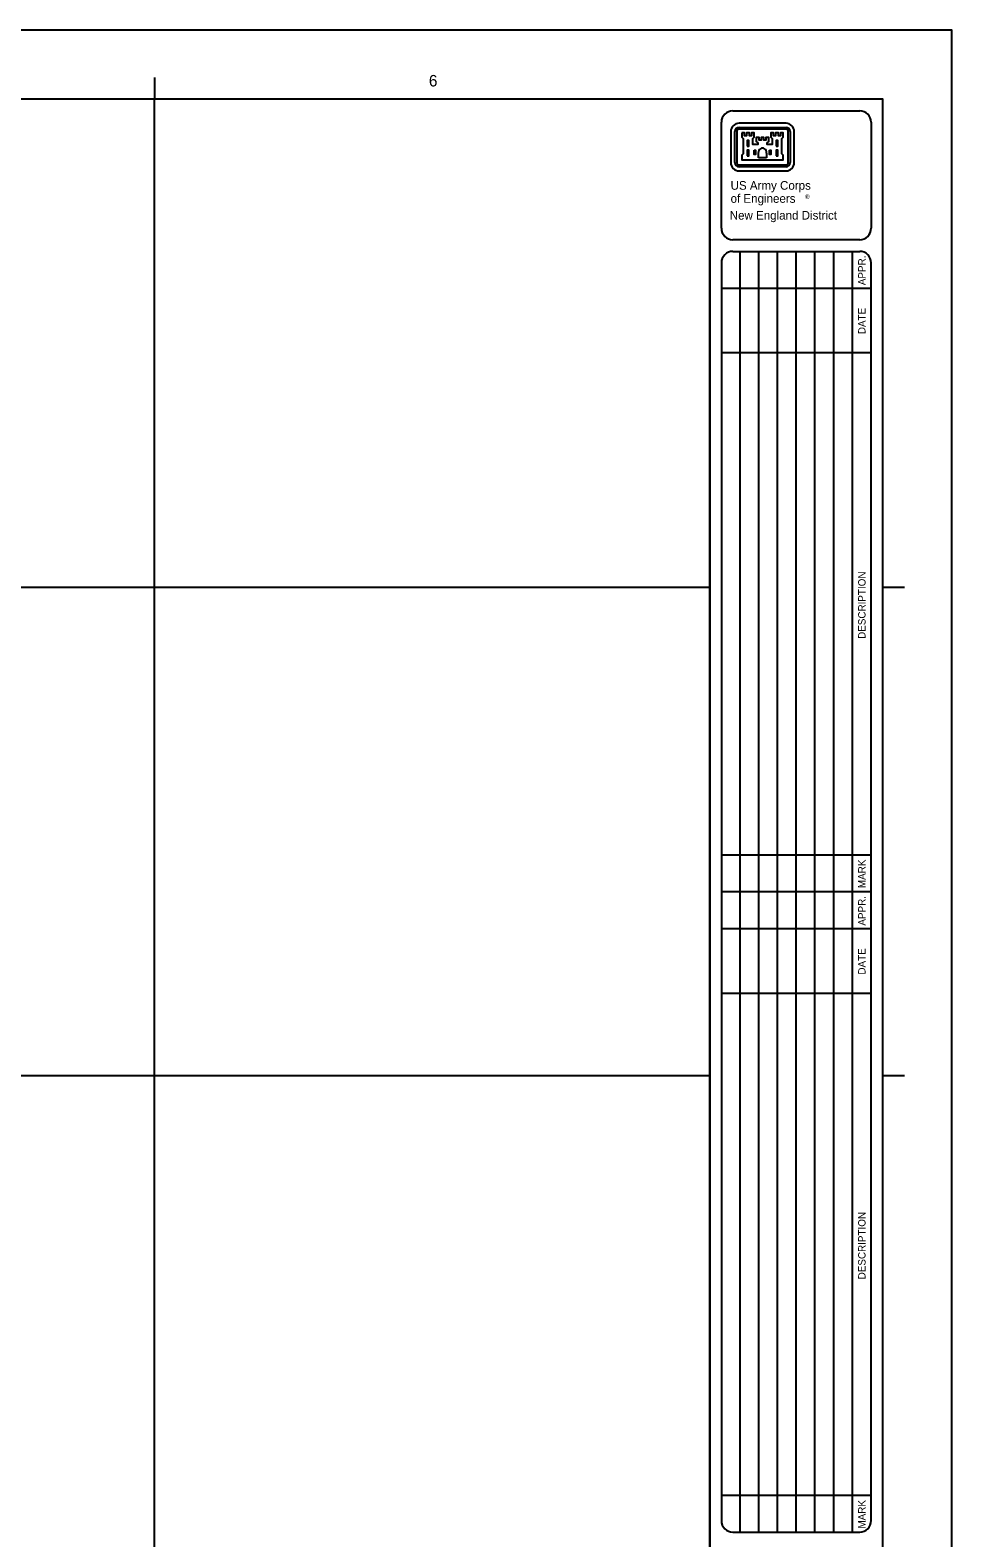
# Model space of a CAD drawing. Extents: x 0 to 3.33, y 0 to 2.33.
# Drawn here: x 2.5 to 3.333, y 0.97 to 2.333 of the extents above; entities that cross this region are included whole.
import ezdxf

# ---------------------------------------------------------------- set-up
doc = ezdxf.new("R2010")
doc.units = 0
for name, color, linetype in [('G-ANNO-NPLT', 7, 'Continuous'), ('G-ANNO-SYMB', 7, 'Continuous'), ('G-ANNO-TEXT', 7, 'Continuous'), ('G-ANNO-TTLB', 7, 'Continuous'), ('G-ANNO-TTLB-GRID', 7, 'Continuous')]:
    doc.layers.add(name, color=color, linetype=linetype)

msp = doc.modelspace()

# ---------------------------------------------------------------- linework, layer by layer
at = {"layer": 'G-ANNO-NPLT'}
msp.add_lwpolyline([(0, 0), (3.3333, 0), (3.3333, 2.3333), (0, 2.3333)], close=True, dxfattribs=at)
at = {"layer": 'G-ANNO-SYMB'}
for p, q in [((3.1334, 2.2416), (3.1334, 2.2135)), ((3.1372, 2.2135), (3.1372, 2.2416)), ((3.1372, 2.2416), (3.1372, 2.2416)), ((3.1388, 2.2416), (3.1388, 2.2135)), ((3.1834, 2.2491), (3.1409, 2.2491)), ((3.1409, 2.2491), (3.1409, 2.2491)), ((3.1409, 2.2454), (3.1834, 2.2454)), ((3.1834, 2.2437), (3.1409, 2.2437)), ((3.1834, 2.2437), (3.1834, 2.2437)), ((3.1855, 2.2135), (3.1855, 2.2416)), ((3.1871, 2.2416), (3.1871, 2.2135)), ((3.1908, 2.2135), (3.1908, 2.2416)), ((3.1409, 2.2114), (3.1834, 2.2114)), ((3.1834, 2.2098), (3.1409, 2.2098)), ((3.1584, 2.2179), (3.1584, 2.2221)), ((3.1659, 2.2179), (3.1584, 2.2179)), ((3.1659, 2.2221), (3.1659, 2.2179)), ((3.1409, 2.206), (3.1834, 2.206))]:
    msp.add_line(p, q, dxfattribs=at)
for points in [[(3.1434, 2.2404), (3.1434, 2.2366), (3.1447, 2.2354), (3.1447, 2.2216), (3.1434, 2.2204), (3.1434, 2.216), (3.1809, 2.216), (3.1809, 2.2204), (3.1796, 2.2216), (3.1796, 2.2354), (3.1809, 2.2366), (3.1809, 2.2404), (3.1784, 2.2404), (3.1784, 2.2379), (3.1765, 2.2379), (3.1765, 2.2404), (3.174, 2.2404), (3.174, 2.2379), (3.1721, 2.2379), (3.1721, 2.2404), (3.1696, 2.2404), (3.1696, 2.2366), (3.1709, 2.2354), (3.1709, 2.2298), (3.1665, 2.2298), (3.1665, 2.2313), (3.1678, 2.2326), (3.1678, 2.2363), (3.1653, 2.2363), (3.1653, 2.2338), (3.1634, 2.2338), (3.1634, 2.2363), (3.1609, 2.2363), (3.1609, 2.2338), (3.159, 2.2338), (3.159, 2.2363), (3.1565, 2.2363), (3.1565, 2.2326), (3.1578, 2.2313), (3.1578, 2.2298), (3.1534, 2.2298), (3.1534, 2.2354), (3.1546, 2.2366), (3.1546, 2.2404), (3.1522, 2.2404), (3.1522, 2.2379), (3.1503, 2.2379), (3.1503, 2.2404), (3.1478, 2.2404), (3.1478, 2.2379), (3.1459, 2.2379), (3.1459, 2.2404), (3.1434, 2.2404)], [(3.1484, 2.2285), (3.1497, 2.2285), (3.1497, 2.2335), (3.1484, 2.2335), (3.1484, 2.2285)], [(3.1484, 2.2198), (3.1497, 2.2198), (3.1497, 2.2248), (3.1484, 2.2248), (3.1484, 2.2198)], [(3.1546, 2.2248), (3.1559, 2.2248), (3.1559, 2.221), (3.1546, 2.221), (3.1546, 2.2248)], [(3.1684, 2.2248), (3.1696, 2.2248), (3.1696, 2.221), (3.1684, 2.221), (3.1684, 2.2248)], [(3.1746, 2.2335), (3.1747, 2.2335)], [(3.1746, 2.2285), (3.1759, 2.2285), (3.1759, 2.2335), (3.1746, 2.2335), (3.1746, 2.2285)], [(3.1746, 2.2198), (3.1759, 2.2198), (3.1759, 2.2248), (3.1746, 2.2248), (3.1746, 2.2198)], [(3.1758, 2.2285), (3.1759, 2.2286)]]:
    msp.add_lwpolyline(points, dxfattribs=at)
for centre, radius, start, end in [((3.1409, 2.2416), 0.00749, 90, 180), ((3.1409, 2.2416), 0.00375, 90, 180), ((3.1409, 2.2416), 0.0021, 90, 180), ((3.1834, 2.2416), 0.00749, 0, 90), ((3.1834, 2.2416), 0.00375, 0, 90), ((3.1834, 2.2416), 0.0021, 0, 90), ((3.1409, 2.2135), 0.00749, 180, 270), ((3.1409, 2.2135), 0.00375, 180, 270), ((3.1409, 2.2135), 0.0021, 180, 270), ((3.1834, 2.2135), 0.00749, 270, 360), ((3.1834, 2.2135), 0.00375, 270, 360), ((3.1834, 2.2135), 0.0021, 270, 360)]:
    msp.add_arc(centre, radius, start, end, dxfattribs=at)
msp.add_ellipse((3.1621, 2.2221), major_axis=(0, 0.00452), ratio=0.827815, start_param=4.712389, end_param=7.853982, dxfattribs=at)
at = {"layer": 'G-ANNO-TTLB'}
for p, q in [((2.6125, 2.2905), (2.6125, 2.2708)), ((3.1354, 2.1333), (3.25, 2.1333)), ((3.1419, 2.1), (3.1419, 2.1333)), ((3.1419, 2.1), (3.1419, 2.1333)), ((3.1589, 2.1), (3.1589, 2.1333)), ((3.1758, 2.1), (3.1758, 2.1333)), ((3.1927, 2.1), (3.1927, 2.1333)), ((3.2096, 2.1), (3.2096, 2.1333)), ((3.2266, 2.1), (3.2266, 2.1333)), ((3.2435, 2.1), (3.2435, 2.1333)), ((3.125, 2.1), (3.1419, 2.1)), ((3.1419, 2.1), (3.1589, 2.1)), ((3.1419, 2.0417), (3.1419, 2.1)), ((3.1589, 2.1), (3.1758, 2.1)), ((3.1589, 2.0417), (3.1589, 2.1)), ((3.1758, 2.1), (3.1927, 2.1)), ((3.1758, 2.0417), (3.1758, 2.1)), ((3.1927, 2.1), (3.2096, 2.1)), ((3.1927, 2.0417), (3.1927, 2.1)), ((3.2096, 2.1), (3.2266, 2.1)), ((3.2096, 2.0417), (3.2096, 2.1)), ((3.2266, 2.1), (3.2435, 2.1)), ((3.2266, 2.0417), (3.2266, 2.1)), ((3.2435, 2.1), (3.2604, 2.1)), ((3.2435, 2.0417), (3.2435, 2.1)), ((3.125, 2.0417), (3.1419, 2.0417)), ((3.1419, 1.5875), (3.1419, 2.0417)), ((3.1419, 2.0417), (3.1589, 2.0417)), ((3.1589, 1.5875), (3.1589, 2.0417)), ((3.1589, 2.0417), (3.1758, 2.0417)), ((3.1758, 1.5875), (3.1758, 2.0417)), ((3.1758, 2.0417), (3.1927, 2.0417)), ((3.1927, 1.5875), (3.1927, 2.0417)), ((3.1927, 2.0417), (3.2096, 2.0417)), ((3.2096, 1.5875), (3.2096, 2.0417)), ((3.2096, 2.0417), (3.2266, 2.0417)), ((3.2266, 1.5875), (3.2266, 2.0417)), ((3.2266, 2.0417), (3.2435, 2.0417)), ((3.2435, 1.5875), (3.2435, 2.0417)), ((3.2435, 2.0417), (3.2604, 2.0417)), ((3.2905, 1.8292), (3.2708, 1.8292)), ((3.125, 1.5875), (3.1419, 1.5875)), ((3.1419, 1.5542), (3.1419, 1.5875)), ((3.1419, 1.5875), (3.1589, 1.5875)), ((3.1589, 1.5542), (3.1589, 1.5875)), ((3.1589, 1.5875), (3.1758, 1.5875)), ((3.1758, 1.5542), (3.1758, 1.5875)), ((3.1758, 1.5875), (3.1927, 1.5875)), ((3.1927, 1.5542), (3.1927, 1.5875)), ((3.1927, 1.5875), (3.2096, 1.5875)), ((3.2096, 1.5542), (3.2096, 1.5875)), ((3.2096, 1.5875), (3.2266, 1.5875)), ((3.2266, 1.5875), (3.2435, 1.5875)), ((3.2266, 1.5542), (3.2266, 1.5875)), ((3.2435, 1.5542), (3.2435, 1.5875)), ((3.2435, 1.5875), (3.2604, 1.5875)), ((3.125, 1.5542), (3.2604, 1.5542)), ((3.1419, 1.5208), (3.1419, 1.5542)), ((3.1419, 1.5208), (3.1419, 1.5542)), ((3.1589, 1.5208), (3.1589, 1.5542)), ((3.1758, 1.5208), (3.1758, 1.5542)), ((3.1927, 1.5208), (3.1927, 1.5542)), ((3.2096, 1.5208), (3.2096, 1.5542)), ((3.2266, 1.5208), (3.2266, 1.5542)), ((3.2435, 1.5208), (3.2435, 1.5542)), ((3.125, 1.5208), (3.1419, 1.5208)), ((3.1419, 1.5208), (3.1589, 1.5208)), ((3.1419, 1.4625), (3.1419, 1.5208)), ((3.1589, 1.4625), (3.1589, 1.5208)), ((3.1589, 1.5208), (3.1758, 1.5208)), ((3.1758, 1.4625), (3.1758, 1.5208)), ((3.1758, 1.5208), (3.1927, 1.5208)), ((3.1927, 1.4625), (3.1927, 1.5208)), ((3.1927, 1.5208), (3.2096, 1.5208)), ((3.2096, 1.4625), (3.2096, 1.5208)), ((3.2096, 1.5208), (3.2266, 1.5208)), ((3.2266, 1.4625), (3.2266, 1.5208)), ((3.2266, 1.5208), (3.2435, 1.5208)), ((3.2435, 1.5208), (3.2604, 1.5208)), ((3.2435, 1.4625), (3.2435, 1.5208)), ((3.125, 1.4625), (3.1419, 1.4625)), ((3.1419, 1.4625), (3.1589, 1.4625)), ((3.1419, 1.0083), (3.1419, 1.4625)), ((3.1589, 1.0083), (3.1589, 1.4625)), ((3.1589, 1.4625), (3.1758, 1.4625)), ((3.1758, 1.0083), (3.1758, 1.4625)), ((3.1758, 1.4625), (3.1927, 1.4625)), ((3.1927, 1.0083), (3.1927, 1.4625)), ((3.1927, 1.4625), (3.2096, 1.4625)), ((3.2096, 1.0083), (3.2096, 1.4625)), ((3.2096, 1.4625), (3.2266, 1.4625)), ((3.2266, 1.0083), (3.2266, 1.4625)), ((3.2266, 1.4625), (3.2435, 1.4625)), ((3.2435, 1.4625), (3.2604, 1.4625)), ((3.2435, 1.0083), (3.2435, 1.4625)), ((3.2905, 1.3875), (3.2708, 1.3875)), ((3.125, 1.0083), (3.1419, 1.0083)), ((3.1419, 0.975), (3.1419, 1.0083)), ((3.1419, 1.0083), (3.1589, 1.0083)), ((3.1589, 0.975), (3.1589, 1.0083)), ((3.1589, 1.0083), (3.1758, 1.0083)), ((3.1758, 0.975), (3.1758, 1.0083)), ((3.1758, 1.0083), (3.1927, 1.0083)), ((3.1927, 0.975), (3.1927, 1.0083)), ((3.1927, 1.0083), (3.2096, 1.0083)), ((3.2096, 0.975), (3.2096, 1.0083)), ((3.2096, 1.0083), (3.2266, 1.0083)), ((3.2266, 0.975), (3.2266, 1.0083)), ((3.2266, 1.0083), (3.2435, 1.0083)), ((3.2435, 1.0083), (3.2604, 1.0083)), ((3.2435, 0.975), (3.2435, 1.0083)), ((3.1354, 0.975), (3.25, 0.975))]:
    msp.add_line(p, q, dxfattribs=at)
for points in [[(0.125, 0.0625), (3.1146, 0.0625), (3.1146, 2.2708), (0.125, 2.2708)], [(3.1146, 0.0625), (3.2708, 0.0625), (3.2708, 2.2708), (3.1146, 2.2708)]]:
    msp.add_lwpolyline(points, close=True, dxfattribs=at)
for points in [[(3.125, 2.1542), (3.125, 2.25)], [(3.1354, 2.2604), (3.25, 2.2604)], [(3.2604, 2.25), (3.2604, 2.1542)], [(3.25, 2.1438), (3.1354, 2.1438)], [(3.125, 2.1229), (3.125, 0.9854)], [(3.2604, 0.9854), (3.2604, 2.1229)]]:
    msp.add_lwpolyline(points, dxfattribs=at)
for centre, start, end in [((3.1354, 2.25), 90, 180), ((3.25, 2.25), 0, 90), ((3.1354, 2.1542), 180, 270), ((3.25, 2.1542), 270, 0), ((3.1354, 2.1229), 90, 180), ((3.25, 2.1229), 0, 90), ((3.1354, 0.9854), 180, 270), ((3.25, 0.9854), 270, 0)]:
    msp.add_arc(centre, 0.0104, start, end, dxfattribs=at)
at = {"layer": 'G-ANNO-TTLB-GRID'}
for p, q in [((2.6125, 0.0625), (2.6125, 2.2708)), ((3.1146, 1.8292), (0.125, 1.8292)), ((3.1146, 1.3875), (0.125, 1.3875))]:
    msp.add_line(p, q, dxfattribs=at)

# ---------------------------------------------------------------- texts
at = {"layer": 'G-ANNO-SYMB'}
for s, height, p in [('US Army Corps', 0.007813, (3.1333, 2.189)), ('of Engineers', 0.007813, (3.1333, 2.1772)), ('®', 0.00417, (3.2006, 2.1806)), ('New England District', 0.007813, (3.1325, 2.162))]:
    msp.add_text(s, height=height, dxfattribs=at).set_placement(p)
at = {"layer": 'G-ANNO-TEXT'}
msp.add_text('6', height=0.0104, dxfattribs=at).set_placement((2.8605, 2.2824))
for s, height, p in [('APPR.', 0.00667, (3.2553, 2.1027)), ('DATE', 0.00667, (3.2553, 2.0584)), ('DESCRIPTION', 0.006667, (3.2553, 1.7828)), ('MARK', 0.00667, (3.2553, 1.5574)), ('APPR.', 0.00667, (3.2553, 1.5235)), ('DATE', 0.00667, (3.2553, 1.4792)), ('DESCRIPTION', 0.006667, (3.2553, 1.2036)), ('MARK', 0.00667, (3.2553, 0.9782))]:
    msp.add_text(s, height=height, rotation=90, dxfattribs=at).set_placement(p)

doc.saveas('drawing.dxf')
